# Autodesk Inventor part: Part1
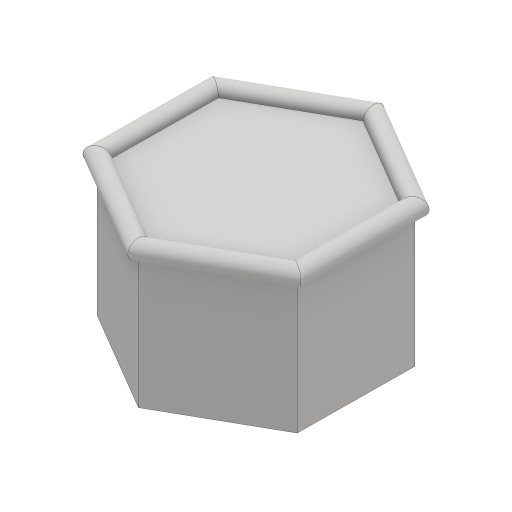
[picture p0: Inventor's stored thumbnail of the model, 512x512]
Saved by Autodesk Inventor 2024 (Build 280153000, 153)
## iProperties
Created: 2015-07
Part Number: Part1
Material: Generic
Document SubType Name: Modeling
Designer: Sandeep
Density: 1 g/cm^3
Appearance: Default
Author: Sandeep
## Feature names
1. Extrusion1
2. Sweep2
## Parameters: d0 = 8 mm, d1 = 0, d4 = 0, d5 = 0
